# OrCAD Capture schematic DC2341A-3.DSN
size Custom; title: HIGH EFFICIENCY STEP-DOWN CONVERTER; rev: 2; company: TM; note: WITH INTEGRATED FETS AND VERY LOW DCR INDUCTOR
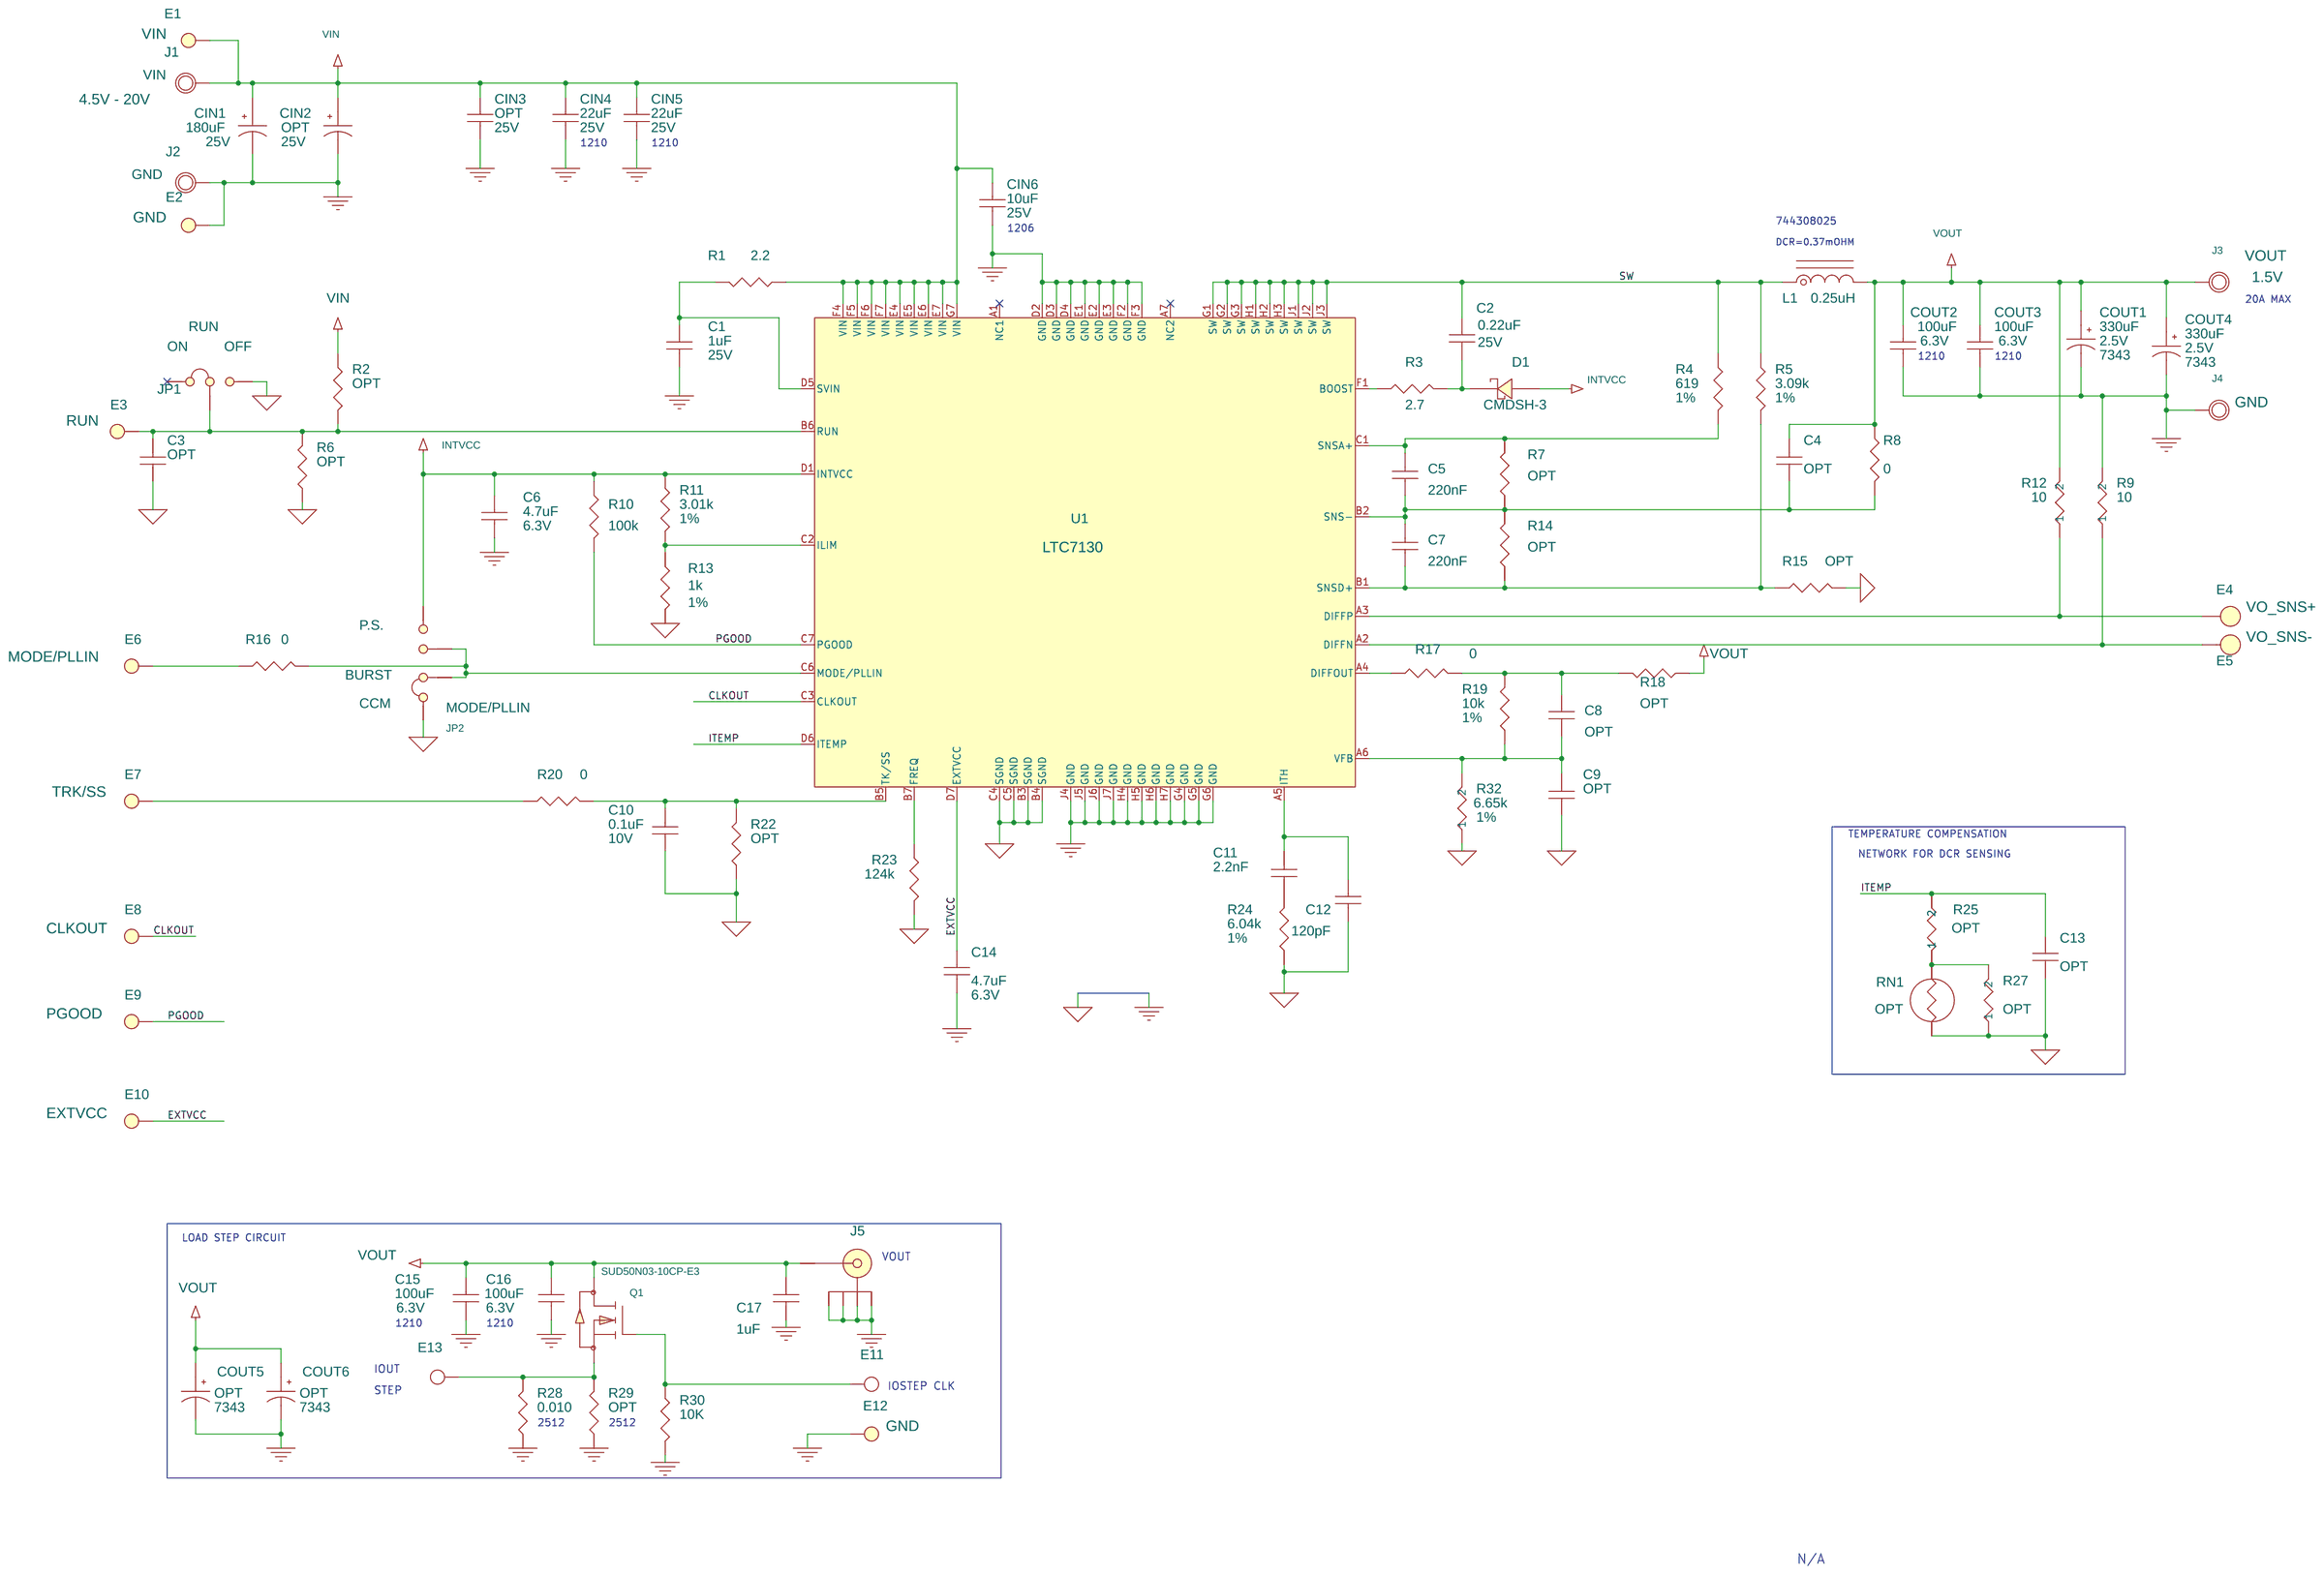
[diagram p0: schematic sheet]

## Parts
C1  1uF  [0805]
C2  0.22uF  [0603]
C3  OPT  [0603]
C4  OPT  [0603]
C5  220nF  [0603]
C6  4.7uF  [0805]
C7  220nF  [0603]
C8  OPT  [0603]
C9  OPT  [0603]
C10  0.1uF  [0603]
C11  2.2nF  [0603]
C12  120pF  [0603]
C13  OPT  [0603]
C14  4.7uF  [0805]
C15  100uF  [1210]
C16  100uF  [1210]
C17  1uF  [0805]
CIN1  180uF  [CAP\SANYO\SVP-F8]
CIN2  OPT  [CAP\SANYO\SVP-F8]
CIN3  OPT  [1210]
CIN4  22uF  [1210]
CIN5  22uF  [1210]
CIN6  10uF  [1206]
COUT1  330uF  [7343]
COUT2  100uF  [1210]
COUT3  100uF  [1210]
COUT4  330uF  [7343]
COUT5  330uF  [7343]
COUT6  330uF  [7343]
D1  CMDSH-3  [SOD-323]
E1  VIN  [TP\MMX\2501-2]
E2  GND  [TP\MMX\2501-2]
E3  RUN  [TP\MMX\2501-2]
E4  VO_SNS+  [TP\MMX\2501-2]
E5  VO_SNS-  [TP\MMX\2501-2]
E6  MODE/PLLIN  [TP\MMX\2501-2]
E7  TRK/SS  [TP\MMX\2501-2]
E8  CLKOUT  [TP\MMX\2501-2]
E9  PGOOD  [TP\MMX\2501-2]
E10  EXTVCC  [TP\MMX\2501-2]
E11  SDA  [TP\MMX\2501-2]
E12  GND  [TP\MMX\2501-2]
E13  SDA  [TP\MMX\2501-2]
J1  VIN  [KEY-575-4]
J2  GND  [KEY-575-4]
J3  VOUT  [KEY-575-4]
J4  GND  [KEY-575-4]
J5  XXX  [BNC]
JP1  RUN  [SIP\3P\2MM]
JP2  MODE/PLLIN  [SIP\4P\2MM]
L1  0.25uH  [IND\VITEC\59P8903]
Q1  SUD50N03-10CP-E3  [TO-252]
R1  2.2  [0603]
R2  OPT  [0603]
R3  2.7  [0603]
R4  619  [0603]
R5  3.09k  [0603]
R6  OPT  [0603]
R7  OPT  [0603]
R8  0  [0603]
R9  10  [0603]
R10  100k  [0603]
R11  3.01k  [0603]
R12  10  [0603]
R13  1k  [0603]
R14  OPT  [0603]
R15  OPT  [0603]
R16  0  [0603]
R17  0  [0603]
R18  OPT  [0603]
R19  10k  [0603]
R20  0  [0603]
R22  OPT  [0603]
R23  124k  [0603]
R24  6.04k  [0603]
R25  OPT  [0603]
R27  OPT  [0603]
R28  0.010  [2512]
R29  OPT  [2512]
R30  10K  [0603]
R32  6.65k  [0603]
RN1  OPT  [0805]
U1  LTC7130  [BGA_63_7.25MM_6.25MM_2.22MM]
XJP1  SHUNT  [NONE]
XJP2  SHUNT  [NONE]

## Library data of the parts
C1 = CAP_NP_1: CAP, 0805 4.7uF 20% 10V X5R; Part Number: TDK C2012X5R1A475M; Voltage: 25V
C2 = CAP_NP_1: CAP, 0603 0.1uF 10% 10V X5R; Part Number: AVX 0603ZD104KAT; Voltage: 25V
C3 C4 C8 C9 C13 = CAP_NP_1: CAP, 0603 OPTION; Part Number: OPTION
C5 C7 = CAP_NP_1: CAP, 0603 220nF 10% 25V X7R; Part Number: TDK C1608X7R1E224K
C6 C14 = CAP_NP_1: CAP, 0805 4.7uF 20% 10V X5R; Part Number: TDK C2012X5R1A475M; Voltage: 6.3V
C10 = CAP_NP_1: CAP, 0603 0.1uF 10% 10V X5R; Part Number: AVX 0603ZD104KAT; Voltage: 10V
C11 = CAP_NP_1: CAP, 0603 1.5nF 5% 50V C0G; Part Number: MURATA GRM1885C1H152JA01D
C12 = CAP_NP_1: CAP, 0603 220pF 10% 25V NPO; Part Number: AVX 06033A221KAT2A
C15-C17 = CAP_NP_0: CAP, 1210 100uF 20% 6.3V X5R; Part Number: TDK C3225X5R0J107M; Voltage: 6.3V
CIN1 CIN2 = CAPACITOR_POL: CAP, 180uF 20% 16V; Part Number: SANYO 16SVP180MX; Voltage: 25V
CIN3-CIN6 = CAP_NP_1: CAP, 1210 10uF 20% 25V X5R; Part Number: TAIYO YUDEN TMK325BJ106MM-T; Voltage: 25V
COUT1 COUT4 = t510x337k010as: CAP, 7343 330uF 20% 2.5V POSCAP; 1st Part Field: 2.5V; 3rd Part Field: POSCAP; Part Number: SANYO 2R5TPE330M9
COUT2 COUT3 = CAP_NP_1: CAP, 1210 100uF 20% 6.3V X5R; Part Number: TDK C3225X5R0J107M; Voltage: 6.3V
COUT5 COUT6 = t510x337k010as: CAP, 7343 330uF 20% 2.5V POSCAP OPTION; 1st Part Field: OPT; 3rd Part Field: POSCAP; Part Number: SANYO 2R5TPE330M9 OPTION
D1 = DIODE_SCHOTTKY31_0: DOIDE, CMDSH-3; Part Number: CENTRAL SEMI CMDSH-3
E1 E2 E6 E12 = T_POINT_R_0: TURRET; Part Number: MILL-MAX 2501-2-00-80-00-00-07-0; STATUS: ?
E3 E7-E10 = T_POINT_R_0: TURRET; Part Number: MILL-MAX 2501-2-00-80-00-00-07-0
E4 E5 = E_0: TURRET; Part Number: MILL-MAX 2501-2-00-80-00-00-07-0
E11 E13 = TP_KEY_1502-2: TURRET; Part Number: MILL-MAX 2501-2-00-80-00-00-07-0
J1 = TP_KEY_1502-2_0: JACK, BANANA; Part Number: KEYSTONE 575-4; STATUS: 4.5V - 20V
J2 = TP_KEY_1502-2_0: JACK, BANANA; Part Number: KEYSTONE 575-4
J3 = TP_KEY_1502-2_0: STUD, TEST PIN; Part Number: PEM KFH-032-10; STATUS: 1.5V
J4 = TP_KEY_1502-2_0: STUD, TEST PIN; Part Number: PEM KFH-032-10
J5 = BNC5-SCH_0: CONN,BNC,5 PINS; Part Number: CONNEX 112404
JP1 = JMPR3: HEADER, 3 PIN; 1: ON; 2: OFF; Part Number: SAMTEC TMM-103-02--L-S
JP2 = JMPR3_0: HEADER, 4PIN; 1: P.S.; 2: BURST; 4: CCM; Part Number: SAMTEC TMM-104-02--L-S
L1 = INDUCTOR_IRON1: IND, 0.33uH; Part Number: WURTH ELEKTRONIK  M744301033
Q1 = SUND50N03_0: XSTR, N-CHANNEL DMOS FET; 5TH PART FIELD: 2N7002TA
R1 R17 R20 = RESISTOR_1: RES, 0603 0 OHM JUMPER 1/10W; Part Number: VISHAY CRC06030000Z0EA; Tolerance: JUMPER
R2 R6 R7 R14 R15 = RESISTOR_1: RES 0603 OPTION; Part Number: OPTION
R3 R8 R16 = RES_0: RES, 0603 0 OHM JUMPER 1/10W; Part Number: VISHAY CRC06030000Z0EA; Tolerance: JUMPER
R4 = RESISTOR_1: RES, 0603 1.24k OHMS 1% 1/10W; Part Number: YAGEO RC0603FR-07931RL; Tolerance: 1%
R5 = RESISTOR_1: RES, 0603 6.19K OHM 1% 1/10W; Part Number: VISHAY CRCW06034K64FKEA; Tolerance: 1%
R9 = R_3: RES, 0603 10 OHMS 5% 1/10W; Part Number: VISHAY CRCW060310R0JNEA
R10 = RESISTOR_1: RES 0603 100K OHMS 1% 1/10W; Part Number: VISHAY CRCW0603100KFKEA; Tol: 1%
R11 = RES_0: RES, 0603 1% 1/10W; Part Number: VISHAY CRCW06033K01FKEA; Tolerance: 1%
R12 = R: RES, 0603 10 OHMS 5% 1/10W; Part Number: VISHAY CRCW060310R0JNEA
R13 = RESISTOR_1: RES 0603 1k OHMS 1% 1/10W; Part Number: VISHAY CRCW06031K00FKEA; Tolerance: 1%
R18 = RESISTOR_1: RES 0603 OPTION; Part Number: OPTION; Tolerance: JUMPER
R19 = RESISTOR_1: RES, 0603 30.1K OHM 1% 1/10W; Part Number: VISHAY CRCW060330K1FKEA; Tolerance: 1%
R22 = RESISTOR_1: RES 0603 OPTION; Part Number: OPTION; Tolerance: 5%
R23 = RESISTOR_1: RES, 0603 100K OHM 5% 1/10W; Part Number: VISHAY CRCW0603100KJNEA
R24 = RESISTOR_1: RES, 0603 10K OHM 1% 1/10W; Part Number: VISHAY CRCW060310K0FKEA; Tol: 1%
R25 = R_2: RES 0603 OPTION; Part Number: OPTION
R27 = R_4: RES 0603 OPTION; Part Number: OPTION
R28 = RESISTOR: RES, 2512 0.010 OHM 5% 1W; Part Number: VISHAY WSL2512R0100FEA; Tol: 5%
R29 = RES_0: RES, 2512 OPTION; Part Number: OPTION
R30 = RES_0: RES, 0603 10K OHMS 5% 1/10W; Part Number: VISHAY CRCE060310K0JNEA
R32 = R_1: RES, 0402 196K OHMS 1% 1/16W; 5%: 1%; Part Number: VISHAY CRCW0402196KFKEA; Tol: 1%
RN1 = RNTC: THERMISTOR, OPTION; Part Number: OPTION
U1 = LTC3830EGN_25: IC, STEP-DOWN CONVERTER; Part Number: LINEAR TECH LTC3866EUF
XJP1 XJP2 = SHUNT: Part Number: SAMTEC 2SN-BK-G

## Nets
GND: C1.2 C6.2 C14.2 C15.1 C16.1 C17.1 CIN1.2 CIN2.2 CIN3.2 CIN4.2 CIN5.2 CIN6.2 COUT1.2 COUT2.2 COUT3.2 COUT4.2 COUT5.2 COUT6.2 E2.1(TP) E12.1(TP) J2.1 J4.1 J5.2 J5.3 J5.4 J5.5 R9.2 R28.1 R29.1 R30.1 U1.D2(GND) U1.D3(GND) U1.D4(GND) U1.E1(GND) U1.E2(GND) U1.E3(GND) U1.F2(GND) U1.F3(GND) U1.G4(GND) U1.G5(GND) U1.G6(GND) U1.H4(GND) U1.H5(GND) U1.H6(GND) U1.H7(GND) U1.J4(GND) U1.J5(GND) U1.J6(GND) U1.J7(GND)
GND_SIGNAL: C3.1 C9.1 C10.1 C12.2 C13.2 JP1.3 JP2.4 R6.2 R13.2 R15.2 R22.1 R23.2 R24.2 R27.1 R32.1 RN1.1 U1.B3(SGND) U1.B4(SGND) U1.C4(SGND) U1.C5(SGND)
VIN: CIN1.1 CIN2.1 CIN3.1 CIN4.1 CIN5.1 CIN6.1 E1.1(TP) J1.1 R1.1 R2.1 U1.E4(VIN) U1.E5(VIN) U1.E6(VIN) U1.E7(VIN) U1.F4(VIN) U1.F5(VIN) U1.F6(VIN) U1.F7(VIN) U1.G7(VIN)
CLKOUT: E8.1(TP) U1.C3(CLKOUT)
EXTVCC: C14.1 E10.1(TP) U1.D7(EXTVCC)
INTVCC: C6.1 D1.2(ANODE) JP2.1 R10.2 R11.1 U1.D1(INTVCC)
ITEMP: C13.1 R25.2 U1.D6(ITEMP)
PGOOD: E9.1(TP) R10.1 U1.C7(PGOOD)
SW: C2.1 L1.1 R4.2 R5.2 U1.G1(SW) U1.G2(SW) U1.G3(SW) U1.H1(SW) U1.H2(SW) U1.H3(SW) U1.J1(SW) U1.J2(SW) U1.J3(SW)
VOUT: C4.2 C15.2 C16.2 C17.2 COUT1.1 COUT2.1 COUT3.1 COUT4.1 COUT5.1 COUT6.1 J3.1 J5.1 L1.2 Q1.3 R8.2 R12.2 R18.1
N307792: E4.1(A) R12.1 U1.A3(DIFFP)
N307808: C4.1 C5.1 C7.2 R7.1 R8.1 R14.2 U1.B2(SNS-)
N309563: C2.2 D1.1(CATHODE) R3.2
N313327: C5.2 R4.1 R7.2 U1.C1(SNSA+)
N313438: C7.1 R5.1 R14.1 R15.1 U1.B1(SNSD+)
N315964: E5.1(A) R9.1 U1.A2(DIFFN)
N320928: R17.2 U1.A4(DIFFOUT)
N321544: C8.2 C9.2 R19.1 R32.2 U1.A6(VFB)
N326011: C8.1 R17.1 R18.2 R19.2
N326941: C11.2 C12.1 U1.A5(ITH)
N329191: C10.2 R20.2 R22.2 U1.B5(TK/SS)
N329239: E7.1(TP) R20.1
N335135: R11.2 R13.1 U1.C2(ILIM)
N338323: JP2.2 JP2.3 R16.2 U1.C6(MODE/PLLIN)
N345798: C3.2 E3.1(TP) JP1.2 R2.2 R6.1 U1.B6(RUN)
N349103: E13.1 Q1.2 R28.2 R29.2
N349175: E11.1 Q1.1 R30.2
N354246: C1.1 R1.2 U1.D5(SVIN)
N359188: E6.1(TP) R16.1
N379281: R25.1 R27.2 RN1.2
N393489: R23.1 U1.B7(FREQ)
N431711: R3.1 U1.F1(BOOST)
N16542745: C11.1 R24.1

Not connected (* = marked no-connect by the designer): JP1 1*; U1 A1(NC1)* A7(NC2)*

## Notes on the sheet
- 1210
- 1210
- 744308025
- 1206
- DCR=0.37mOHM
- 20A MAX
- 1210
- 1210
- TEMPERATURE COMPENSATION
- NETWORK FOR DCR SENSING
- LOAD STEP CIRCUIT
- VOUT
- 1210
- 1210
- IOUT
- STEP
- IOSTEP CLK
- 2512
- 2512
- N/A
